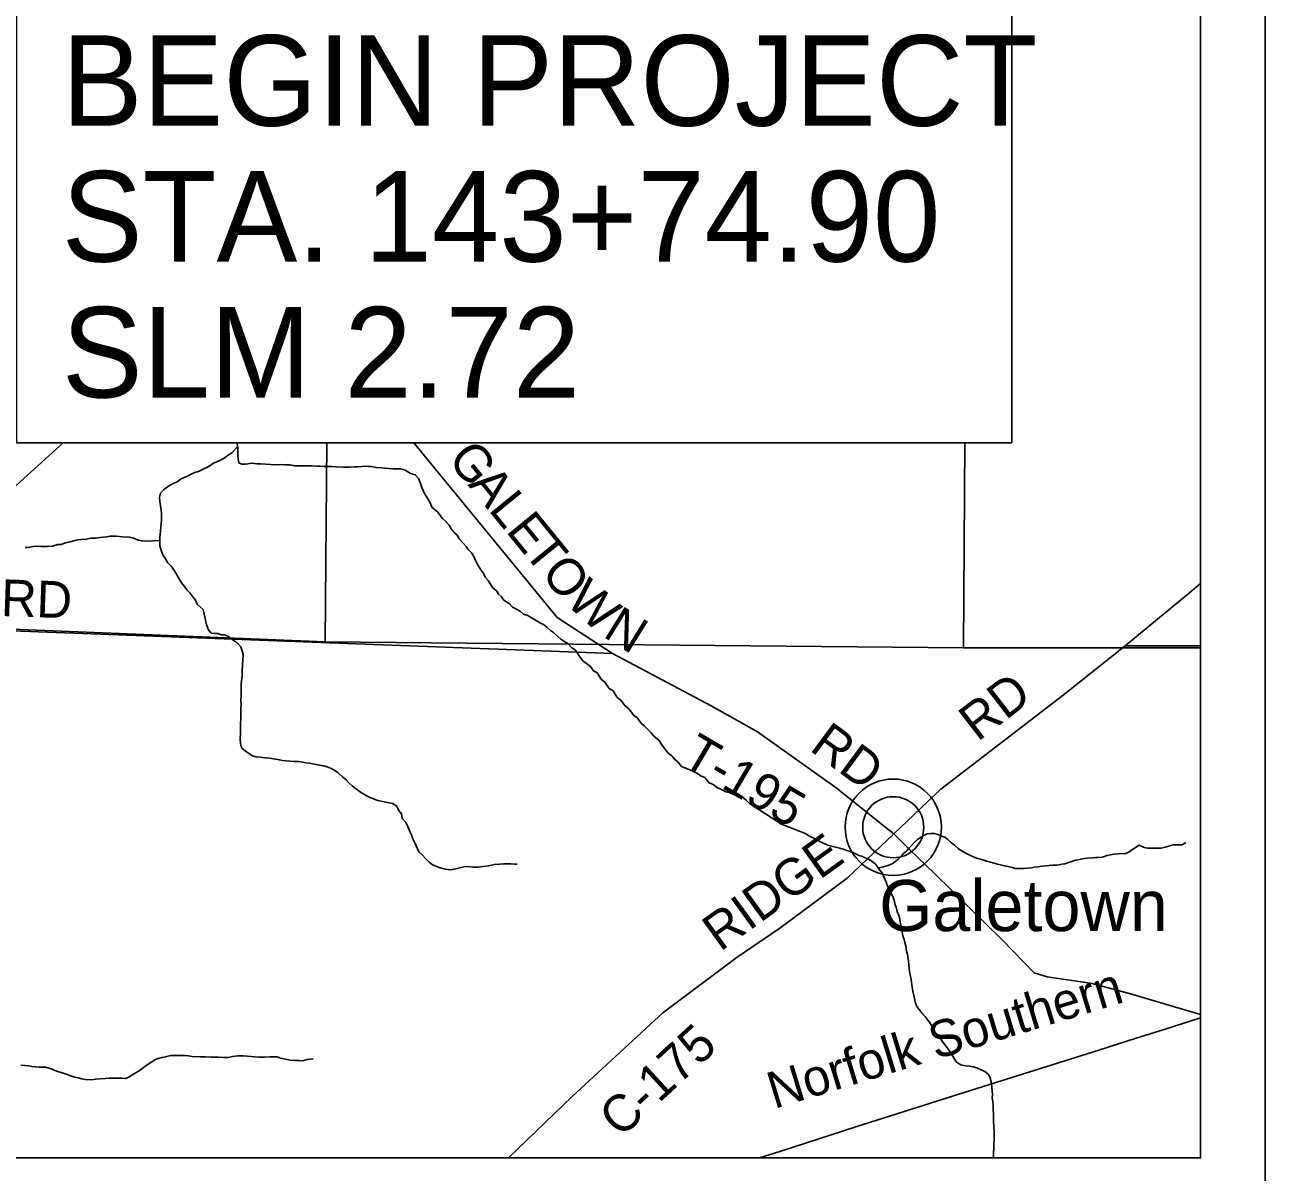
# Model space of a CAD drawing. Extents: x 0 to 34, y 0 to 22.
# Drawn here: x 28.499 to 30.417, y 14.078 to 15.851 of the extents above; entities that cross this region are included whole.
import ezdxf

# ---------------------------------------------------------------- set-up
doc = ezdxf.new("R2010")
doc.units = 0
for name, color, linetype in [('GM_X_County_Road', 7, 'Continuous'), ('GM_X_County_Road_Text', 7, 'Continuous'), ('GM_X_Minor_River', 7, 'Continuous'), ('GM_X_Rail_Line', 7, 'Continuous'), ('GM_X_Rail_Line_Text', 7, 'Continuous'), ('GM_X_Section', 7, 'Continuous'), ('GM_X_Township_Road', 7, 'Continuous'), ('GM_X_Township_Road_Text', 7, 'Continuous'), ('GM_X_Unincorporated', 7, 'Continuous'), ('GM_X_Unincorporated_Location', 7, 'Continuous'), ('GM_X_Unincorporated_Text', 7, 'Continuous'), ('SH_Data', 7, 'Continuous'), ('SH_Text', 7, 'Continuous')]:
    doc.layers.add(name, color=color, linetype=linetype)

msp = doc.modelspace()

# ---------------------------------------------------------------- linework, layer by layer
at = {"layer": 'GM_X_County_Road'}
msp.add_lwpolyline([(29.2468, 14.1), (29.3452, 14.1946), (29.4855, 14.3242), (29.6004, 14.4101), (29.6664, 14.455), (29.7704, 14.5321), (29.8427, 14.6006), (29.9152, 14.6701), (30.1043, 14.8152), (30.2003, 14.8913), (30.3004, 14.974), (30.3167, 14.9878)], dxfattribs=at)
at = {"layer": 'GM_X_Minor_River'}
for points in [[(28.828, 15.1992), (28.8193, 15.1898), (28.8132, 15.186), (28.8071, 15.1815), (28.7983, 15.1767), (28.7915, 15.1741), (28.7815, 15.1678), (28.7758, 15.1652), (28.7674, 15.1611), (28.7621, 15.1596), (28.7564, 15.157), (28.7507, 15.1537), (28.7407, 15.1496), (28.7346, 15.1451), (28.7293, 15.1429), (28.7239, 15.1399), (28.719, 15.1366), (28.7132, 15.1324), (28.709, 15.1276), (28.707, 15.1215), (28.7077, 15.1147), (28.7098, 15.101), (28.7105, 15.096), (28.7104, 15.0858), (28.71, 15.0808), (28.7095, 15.0748), (28.7087, 15.0691), (28.7083, 15.0642), (28.7079, 15.0592), (28.7077, 15.0459), (28.7095, 15.041), (28.7125, 15.0322), (28.7155, 15.0276), (28.7203, 15.02), (28.7259, 15.0142), (28.7289, 15.0093), (28.7334, 15.002), (28.7367, 14.9967), (28.7412, 14.9886), (28.7461, 14.9833), (28.7494, 14.9779), (28.7539, 14.9733), (28.7588, 14.9672), (28.7629, 14.9618), (28.7655, 14.9561), (28.77, 14.9515), (28.7749, 14.9477), (28.7799, 14.9237), (28.7832, 14.9161), (28.7873, 14.9111), (28.793, 14.9106), (28.7976, 14.9106), (28.8029, 14.9086), (28.8078, 14.9082), (28.8131, 14.9063), (28.818, 14.9024), (28.8229, 14.8993), (28.8274, 14.8959), (28.833, 14.8897), (28.8352, 14.8836), (28.8367, 14.8779), (28.8362, 14.8684), (28.8354, 14.8635), (28.8352, 14.8502), (28.8348, 14.8449), (28.8335, 14.8332), (28.8337, 14.8221), (28.8337, 14.8149), (28.8332, 14.8062), (28.8335, 14.8001), (28.8331, 14.7952), (28.833, 14.7865), (28.8327, 14.7633), (28.8322, 14.7569), (28.8321, 14.747), (28.8324, 14.7417), (28.8332, 14.7371), (28.835, 14.7325), (28.844, 14.726), (28.8508, 14.7214), (28.8565, 14.7198), (28.8622, 14.7193), (28.8705, 14.7181), (28.8773, 14.7177), (28.8868, 14.7164), (28.8925, 14.7152), (28.8974, 14.7144), (28.9087, 14.7131), (28.9148, 14.7127), (28.9228, 14.7126), (28.9288, 14.7118), (28.9337, 14.7106), (28.9394, 14.7102), (28.9466, 14.7086), (28.9519, 14.7077), (28.9606, 14.7058), (28.9667, 14.7046), (28.9716, 14.7022), (28.9765, 14.6999), (28.9833, 14.6949), (28.9908, 14.6884)], [(28.8276, 15.2053), (28.8275, 15.2033), (28.8282, 15.198), (28.8285, 15.1912), (28.8284, 15.1866), (28.8287, 15.1802), (28.8298, 15.1745), (28.8347, 15.1721)], [(28.8347, 15.1721), (28.84, 15.1725), (28.8506, 15.1739), (28.8578, 15.1726), (28.8635, 15.1726), (28.8715, 15.1721), (28.8787, 15.1717), (28.8863, 15.1712), (28.8946, 15.1715), (28.9018, 15.171), (28.909, 15.171), (28.9158, 15.1697), (28.9344, 15.1696), (28.9424, 15.1698), (28.9504, 15.1694), (28.956, 15.1693), (28.9617, 15.1689), (28.9739, 15.1687), (28.9811, 15.1679), (28.9917, 15.1678), (28.9966, 15.1674), (29.0012, 15.1677), (29.0088, 15.168), (29.0137, 15.1683), (29.0198, 15.1686), (29.0251, 15.169), (29.0304, 15.1685), (29.0353, 15.1685), (29.0421, 15.1673), (29.0508, 15.1664), (29.0558, 15.166), (29.0679, 15.1651), (29.08, 15.165), (29.0868, 15.163), (29.0951, 15.158), (29.1023, 15.1556), (29.1075, 15.1499), (29.1105, 15.1422), (29.1127, 15.1361), (29.1171, 15.127), (29.122, 15.1189), (29.1257, 15.1125), (29.1283, 15.1056), (29.1373, 15.0979), (29.144, 15.0887), (29.1489, 15.0849), (29.1549, 15.078), (29.1583, 15.0722), (29.1631, 15.0661), (29.1676, 15.0627), (29.1706, 15.0566), (29.1766, 15.0504), (29.1811, 15.0451), (29.1844, 15.0401), (29.1901, 15.0347), (29.193, 15.0294), (29.1964, 15.0225), (29.2001, 15.0156), (29.2042, 15.0087), (29.2075, 15.0041), (29.2105, 14.9977), (29.2154, 14.9923), (29.2221, 14.9816), (29.2288, 14.9758), (29.2314, 14.9712), (29.236, 14.9674), (29.2389, 14.9628), (29.2442, 14.959), (29.2487, 14.9559), (29.2528, 14.9513), (29.26, 14.9474), (29.2653, 14.9443), (29.2698, 14.9405), (29.2766, 14.9381), (29.2815, 14.935), (29.2898, 14.9308), (29.2962, 14.9265), (29.3011, 14.9242), (29.306, 14.9203), (29.3116, 14.915), (29.3165, 14.9123), (29.3233, 14.9057), (29.3278, 14.9019), (29.3323, 14.8988), (29.3383, 14.8949), (29.3447, 14.8884), (29.3503, 14.8849), (29.357, 14.8746), (29.3619, 14.8681), (29.3694, 14.8627), (29.3743, 14.8589), (29.3777, 14.8535), (29.3837, 14.8497), (29.39, 14.8401), (29.3957, 14.8355), (29.4024, 14.8255), (29.4084, 14.8217), (29.4147, 14.8117), (29.4204, 14.8075), (29.4264, 14.7991), (29.4335, 14.7937)], [(28.7078, 15.0543), (28.6884, 15.0534), (28.6801, 15.0535), (28.6744, 15.055), (28.6673, 15.0581), (28.6601, 15.0594), (28.6498, 15.0599), (28.64, 15.0611), (28.6305, 15.0608), (28.6259, 15.0601), (28.6153, 15.0587), (28.6085, 15.058), (28.6012, 15.0577), (28.594, 15.0563), (28.586, 15.0556), (28.5811, 15.0553), (28.5762, 15.0542), (28.5693, 15.052), (28.5621, 15.0505), (28.5552, 15.0483), (28.5503, 15.048), (28.5419, 15.0454), (28.5343, 15.0451), (28.5298, 15.0452), (28.5241, 15.0449), (28.5196, 15.0453), (28.512, 15.045), (28.5044, 15.0436), (28.4994, 15.0432)], [(29.4335, 14.7937), (29.4402, 14.7845), (29.4459, 14.7803), (29.4522, 14.7715), (29.4567, 14.768), (29.462, 14.7619), (29.4676, 14.7569), (29.4721, 14.7511), (29.4792, 14.7458), (29.4848, 14.737), (29.4938, 14.7255), (29.4991, 14.7216), (29.5039, 14.7155), (29.5084, 14.712), (29.5144, 14.7051), (29.5193, 14.7028), (29.5269, 14.6997), (29.5325, 14.697), (29.5378, 14.6946), (29.545, 14.69), (29.5503, 14.6877), (29.557, 14.6796), (29.563, 14.6769), (29.5698, 14.6719), (29.5751, 14.6699), (29.5826, 14.6657), (29.5879, 14.6645), (29.5947, 14.6614), (29.6012, 14.6598), (29.6087, 14.6574), (29.6136, 14.6536), (29.6196, 14.6478), (29.6689, 14.6158)], [(28.9908, 14.6884), (28.9957, 14.6841), (29.0005, 14.6791), (29.005, 14.6753), (29.0103, 14.6707), (29.0193, 14.6641), (29.0242, 14.6614), (29.0295, 14.6587), (29.0382, 14.6548), (29.0446, 14.6525), (29.0548, 14.6501), (29.0624, 14.6489), (29.0677, 14.6477), (29.0741, 14.6434), (29.0767, 14.6373), (29.0812, 14.6316), (29.0822, 14.6247), (29.0882, 14.6182), (29.0912, 14.6121), (29.0945, 14.6045), (29.0967, 14.5991), (29.0989, 14.593), (29.1041, 14.5824), (29.1082, 14.5732), (29.1131, 14.5686), (29.1183, 14.5625), (29.1239, 14.5571), (29.1292, 14.5529), (29.1413, 14.5482), (29.1492, 14.5462), (29.1553, 14.5454), (29.1598, 14.5457), (29.1674, 14.5471), (29.1777, 14.5497), (29.1849, 14.5504), (29.1917, 14.5492), (29.1997, 14.5491), (29.2069, 14.5505), (29.2157, 14.5512), (29.2248, 14.5534), (29.2335, 14.554), (29.2392, 14.5547), (29.2506, 14.5546), (29.2555, 14.5542), (29.2601, 14.5541)], [(29.6689, 14.6158), (29.7072, 14.6011), (29.711, 14.5977), (29.7232, 14.592), (29.7281, 14.589), (29.7323, 14.5867), (29.7361, 14.5852), (29.7407, 14.5834), (29.7445, 14.5822), (29.7487, 14.5811), (29.7593, 14.5785), (29.7658, 14.5766), (29.7715, 14.5748), (29.7753, 14.5733), (29.7791, 14.5718), (29.784, 14.5699), (29.7882, 14.5676), (29.7928, 14.5661), (29.8019, 14.5624), (29.8069, 14.5598), (29.8107, 14.5571), (29.8149, 14.5533), (29.8206, 14.5454), (29.8248, 14.5397), (29.8286, 14.5306), (29.8306, 14.5268), (29.8317, 14.523), (29.8336, 14.5181), (29.8359, 14.5139), (29.8398, 14.5063), (29.8413, 14.5022), (29.8429, 14.4984), (29.8448, 14.4912), (29.8459, 14.4874), (29.8479, 14.4809), (29.8502, 14.4745), (29.8517, 14.4696), (29.8525, 14.4642), (29.8533, 14.4601), (29.8549, 14.4521), (29.8553, 14.4483), (29.8568, 14.4418), (29.8584, 14.4373), (29.8595, 14.4331), (29.8614, 14.4255), (29.8618, 14.4214), (29.8634, 14.4164), (29.8642, 14.4111), (29.8654, 14.4039), (29.8658, 14.3978), (29.8662, 14.3929), (29.8666, 14.3883), (29.8677, 14.3826), (29.8693, 14.3762), (29.8709, 14.3633), (29.8724, 14.3549), (29.8732, 14.3511), (29.8748, 14.3435), (29.8759, 14.339), (29.8782, 14.3337), (29.8836, 14.3265), (29.887, 14.3227), (29.8912, 14.3186), (29.8947, 14.3136), (29.8977, 14.3095), (29.9019, 14.303), (29.9054, 14.2954), (29.9107, 14.2883), (29.9157, 14.2826), (29.9195, 14.2777), (29.9249, 14.2701), (29.9298, 14.264), (29.934, 14.2572), (29.9363, 14.2527), (29.9394, 14.2477), (29.9463, 14.244), (29.9535, 14.2421), (29.9592, 14.2418), (29.9652, 14.2407), (29.9706, 14.2392), (29.9774, 14.2362), (29.9831, 14.2335), (29.9877, 14.2301), (29.9908, 14.2252), (29.9927, 14.2195), (29.9935, 14.2146), (29.9943, 14.2085), (29.9947, 14.2032), (29.9951, 14.1982), (29.9947, 14.1925), (29.9955, 14.1869), (29.9959, 14.1812), (29.9959, 14.1755), (29.9964, 14.1675), (29.9968, 14.1629), (29.9968, 14.1565), (29.9972, 14.1485), (29.9976, 14.1409), (29.9977, 14.1284), (29.997, 14.12), (29.997, 14.1147)], [(29.8189, 14.5477), (29.8297, 14.5511), (29.8335, 14.5519), (29.8399, 14.5546), (29.8456, 14.5588), (29.8494, 14.5619), (29.8539, 14.5661), (29.8577, 14.5703), (29.8626, 14.5748), (29.8664, 14.579), (29.8698, 14.5828), (29.8747, 14.5878), (29.8792, 14.592), (29.8837, 14.5954), (29.889, 14.5985), (29.8943, 14.6008), (29.8997, 14.6016), (29.9053, 14.6016), (29.9095, 14.6005), (29.916, 14.5971), (29.9213, 14.5956), (29.9259, 14.5922), (29.9301, 14.5881), (29.9362, 14.5832), (29.9423, 14.5779), (29.9518, 14.5722), (29.9571, 14.5692), (29.9613, 14.5673), (29.9678, 14.5643), (29.972, 14.5628), (29.9765, 14.5617), (29.9815, 14.5602), (29.986, 14.5587), (29.9921, 14.5572), (29.9974, 14.5557), (30.0028, 14.5539), (30.0077, 14.5527), (30.0138, 14.5516), (30.0259, 14.5486), (30.0301, 14.5475), (30.0339, 14.5472), (30.0438, 14.5472), (30.0495, 14.5476), (30.0556, 14.5484), (30.0597, 14.5492), (30.0654, 14.55), (30.0719, 14.5508), (30.0772, 14.5515), (30.0825, 14.552), (30.0886, 14.5524), (30.0942, 14.5524), (30.0984, 14.5528), (30.1022, 14.5539), (30.1075, 14.5547), (30.1128, 14.5563), (30.1178, 14.5582), (30.1234, 14.5601), (30.1272, 14.5609), (30.1318, 14.5617), (30.1367, 14.5625), (30.142, 14.5633), (30.15, 14.5637), (30.1542, 14.5641), (30.158, 14.5641), (30.1644, 14.5649), (30.1682, 14.5657), (30.172, 14.5672), (30.1773, 14.5684), (30.183, 14.5695), (30.1883, 14.5699), (30.1925, 14.5703), (30.1989, 14.57), (30.2061, 14.5723), (30.2118, 14.5773), (30.2171, 14.5803), (30.2213, 14.5834), (30.2262, 14.5815), (30.23, 14.5796), (30.2346, 14.5789), (30.2414, 14.5785), (30.2456, 14.5789), (30.2501, 14.5786), (30.2558, 14.5786), (30.2619, 14.5802), (30.2691, 14.5825), (30.2744, 14.5836), (30.2789, 14.584), (30.2846, 14.5841), (30.2884, 14.5837), (30.2941, 14.5872)], [(28.5157, 14.2406), (28.5214, 14.2401), (28.5267, 14.2404), (28.5312, 14.24), (28.5396, 14.2376), (28.5494, 14.2337), (28.5539, 14.2322), (28.5645, 14.229), (28.5713, 14.2263), (28.5762, 14.2247), (28.5815, 14.2235), (28.5872, 14.2223), (28.5925, 14.2211), (28.6023, 14.2207), (28.6088, 14.2217), (28.6149, 14.2224), (28.6236, 14.2227), (28.6293, 14.2234), (28.6422, 14.2233), (28.649, 14.2232), (28.6547, 14.2227), (28.6597, 14.2246), (28.6688, 14.2306), (28.6757, 14.2343), (28.6826, 14.2395), (28.6883, 14.244), (28.6952, 14.2485), (28.7002, 14.2515), (28.7047, 14.2537), (28.7112, 14.2552), (28.7162, 14.2563), (28.7245, 14.2581), (28.7348, 14.2583), (28.7405, 14.2583), (28.7458, 14.2582), (28.7518, 14.2578), (28.7579, 14.2569), (28.77, 14.2561), (28.778, 14.2563), (28.7871, 14.2555), (28.7973, 14.2554), (28.806, 14.2549), (28.8136, 14.2552), (28.8205, 14.2567), (28.8281, 14.2577), (28.8368, 14.2576), (28.8432, 14.2572), (28.8489, 14.2567), (28.8542, 14.2559), (28.8607, 14.2558), (28.8694, 14.2557), (28.8777, 14.256), (28.8842, 14.2563), (28.8891, 14.2559), (28.8944, 14.2543), (28.9046, 14.252), (28.9099, 14.2511), (28.9171, 14.2507), (28.9228, 14.2506), (28.9285, 14.2502), (28.9357, 14.252), (28.9403, 14.2527), (28.9449, 14.253)], [(28.493, 14.2431), (28.5051, 14.2422), (28.51, 14.2414), (28.5157, 14.2406)], [(29.997, 14.1147), (29.9967, 14.109), (29.9967, 14.1037), (29.996, 14.1)]]:
    msp.add_lwpolyline(points, dxfattribs=at)
at = {"layer": 'GM_X_Rail_Line'}
for points in [[(27.3262, 14.1), (27.337, 14.1097), (27.6409, 14.3774), (27.9444, 14.6491), (28.2526, 14.9288), (28.5584, 15.2053)], [(29.6348, 14.1), (29.6661, 14.1099), (29.7838, 14.1479), (29.953, 14.2017), (30.1596, 14.2667), (30.2174, 14.285), (30.2605, 14.2983), (30.3167, 14.3163)]]:
    msp.add_lwpolyline(points, dxfattribs=at)
at = {"layer": 'GM_X_Section'}
for points in [[(28.966, 15.2053), (28.9636, 14.8975), (27.9429, 14.9391), (27.9584, 15.9108), (28.4862, 15.9049)], [(29.9522, 15.2053), (29.9501, 14.8885), (30.3167, 14.8883), (30.3167, 15.899), (30.0249, 15.8995)], [(29.9522, 15.2053), (29.9501, 14.8885), (28.9636, 14.8975), (28.966, 15.2053)]]:
    msp.add_lwpolyline(points, dxfattribs=at)
at = {"layer": 'GM_X_Township_Road'}
msp.add_line((30.2003, 14.8913), (30.3167, 14.8914), dxfattribs=at)
for points in [[(29.8351, 14.6067), (29.7534, 14.6718), (29.6318, 14.7584), (29.5603, 14.7986), (29.4075, 14.8797), (29.3218, 14.9354), (29.1003, 15.2053)], [(27.457, 14.957), (27.9464, 14.9347), (29.4075, 14.8797)], [(30.3167, 14.3215), (30.2086, 14.3534), (30.1491, 14.3694), (30.0796, 14.3798), (30.0595, 14.3858), (30.0103, 14.4363), (29.9055, 14.5397), (29.8668, 14.5767), (29.8427, 14.6006), (29.8351, 14.6067)]]:
    msp.add_lwpolyline(points, dxfattribs=at)
at = {"layer": 'GM_X_Unincorporated'}
for radius in [0.0744, 0.0472]:
    msp.add_circle((29.8416, 14.6111), radius, dxfattribs=at)
at = {"layer": 'GM_X_Unincorporated_Location'}
msp.add_line((29.8416, 14.6111), (29.8416, 14.6111), dxfattribs=at)
at = {"layer": 'SH_Data'}
for points in [[(23.4167, 21), (30.4167, 21), (30.4167, 14), (23.4167, 14)], [(23.5167, 20.9), (30.3167, 20.9), (30.3167, 14.1), (23.5167, 14.1)], [(28.4862, 15.9053), (30.0249, 15.9053), (30.0249, 15.2053), (28.4862, 15.2053)]]:
    msp.add_lwpolyline(points, close=True, dxfattribs=at)

# ---------------------------------------------------------------- texts
at = {"layer": 'GM_X_County_Road_Text'}
for s, rotation, p in [('RD', 37.6583, (29.972, 14.7422)), ('RIDGE', 35.8092, (29.5739, 14.418)), ('C-175', 42.6625, (29.4201, 14.1294))]:
    msp.add_text(s, height=0.05682, rotation=rotation, dxfattribs=at).set_placement(p)
at = {"layer": 'GM_X_Rail_Line_Text'}
msp.add_text('Norfolk Southern', height=0.056629, rotation=16.9809, dxfattribs=at).set_placement((29.6575, 14.1754))
at = {"layer": 'GM_X_Township_Road_Text'}
for s, height, rotation, p in [('G', 0.0568, 309.2384, (29.1513, 15.1791)), ('A', 0.0568, 309.2373, (29.183, 15.1404)), ('L', 0.0568, 309.2383, (29.2146, 15.1017)), ('E', 0.0568, 309.2388, (29.2415, 15.0688)), ('T', 0.0568, 309.2388, (29.2684, 15.0359)), ('O', 0.0568, 309.3969, (29.2954, 15.0028)), ('W', 0.0568, 317.7868, (29.3334, 14.9576)), ('RD', 0.05682, 358.0252, (28.4615, 14.9376)), ('N', 0.0568, 328.1353, (29.3911, 14.9066)), ('RD', 0.05682, 323.4237, (29.7105, 14.7309)), ('T-195', 0.05682, 329.4795, (29.5121, 14.7095))]:
    msp.add_text(s, height=height, rotation=rotation, dxfattribs=at).set_placement(p)
at = {"layer": 'GM_X_Unincorporated_Text'}
msp.add_text('Galetown', height=0.07898, rotation=0, dxfattribs=at).set_placement((29.8199, 14.4505))
at = {"layer": 'SH_Text'}
for s, p in [('BEGIN PROJECT', (28.5562, 15.6953)), ('STA. 143+74.90', (28.5562, 15.4853)), ('SLM 2.72', (28.5562, 15.2753))]:
    msp.add_text(s, height=0.14, dxfattribs=at).set_placement(p)

doc.saveas('drawing.dxf')
